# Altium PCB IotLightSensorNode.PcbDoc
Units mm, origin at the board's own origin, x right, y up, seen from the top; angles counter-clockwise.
Board outline 63 x 63 mm, 2 copper layers (Top Layer, Bottom Layer); 28 components, 22 nets, 90 pads, 15 vias.
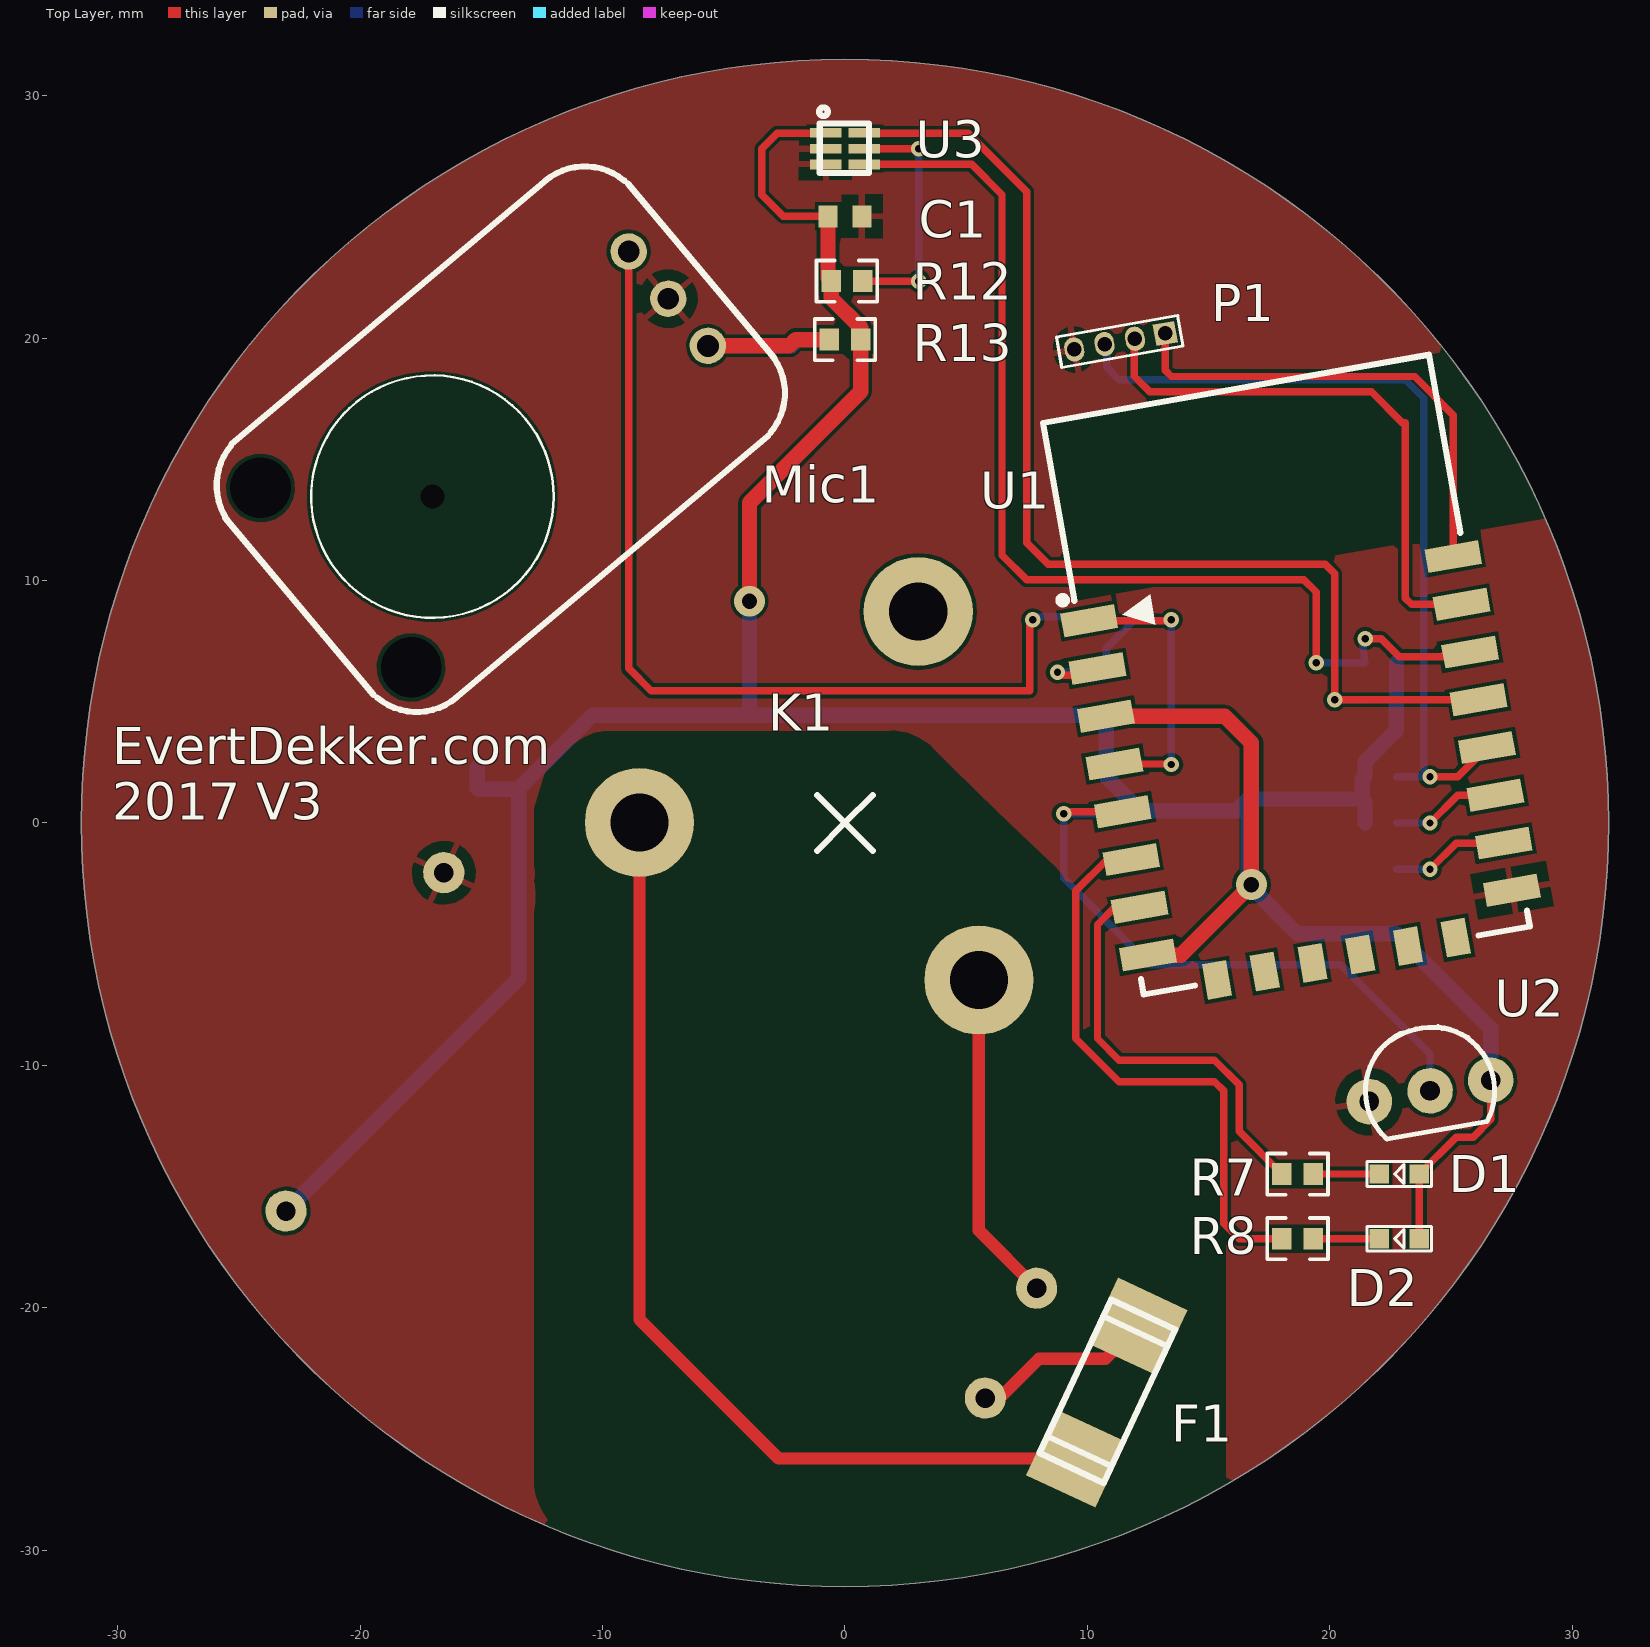
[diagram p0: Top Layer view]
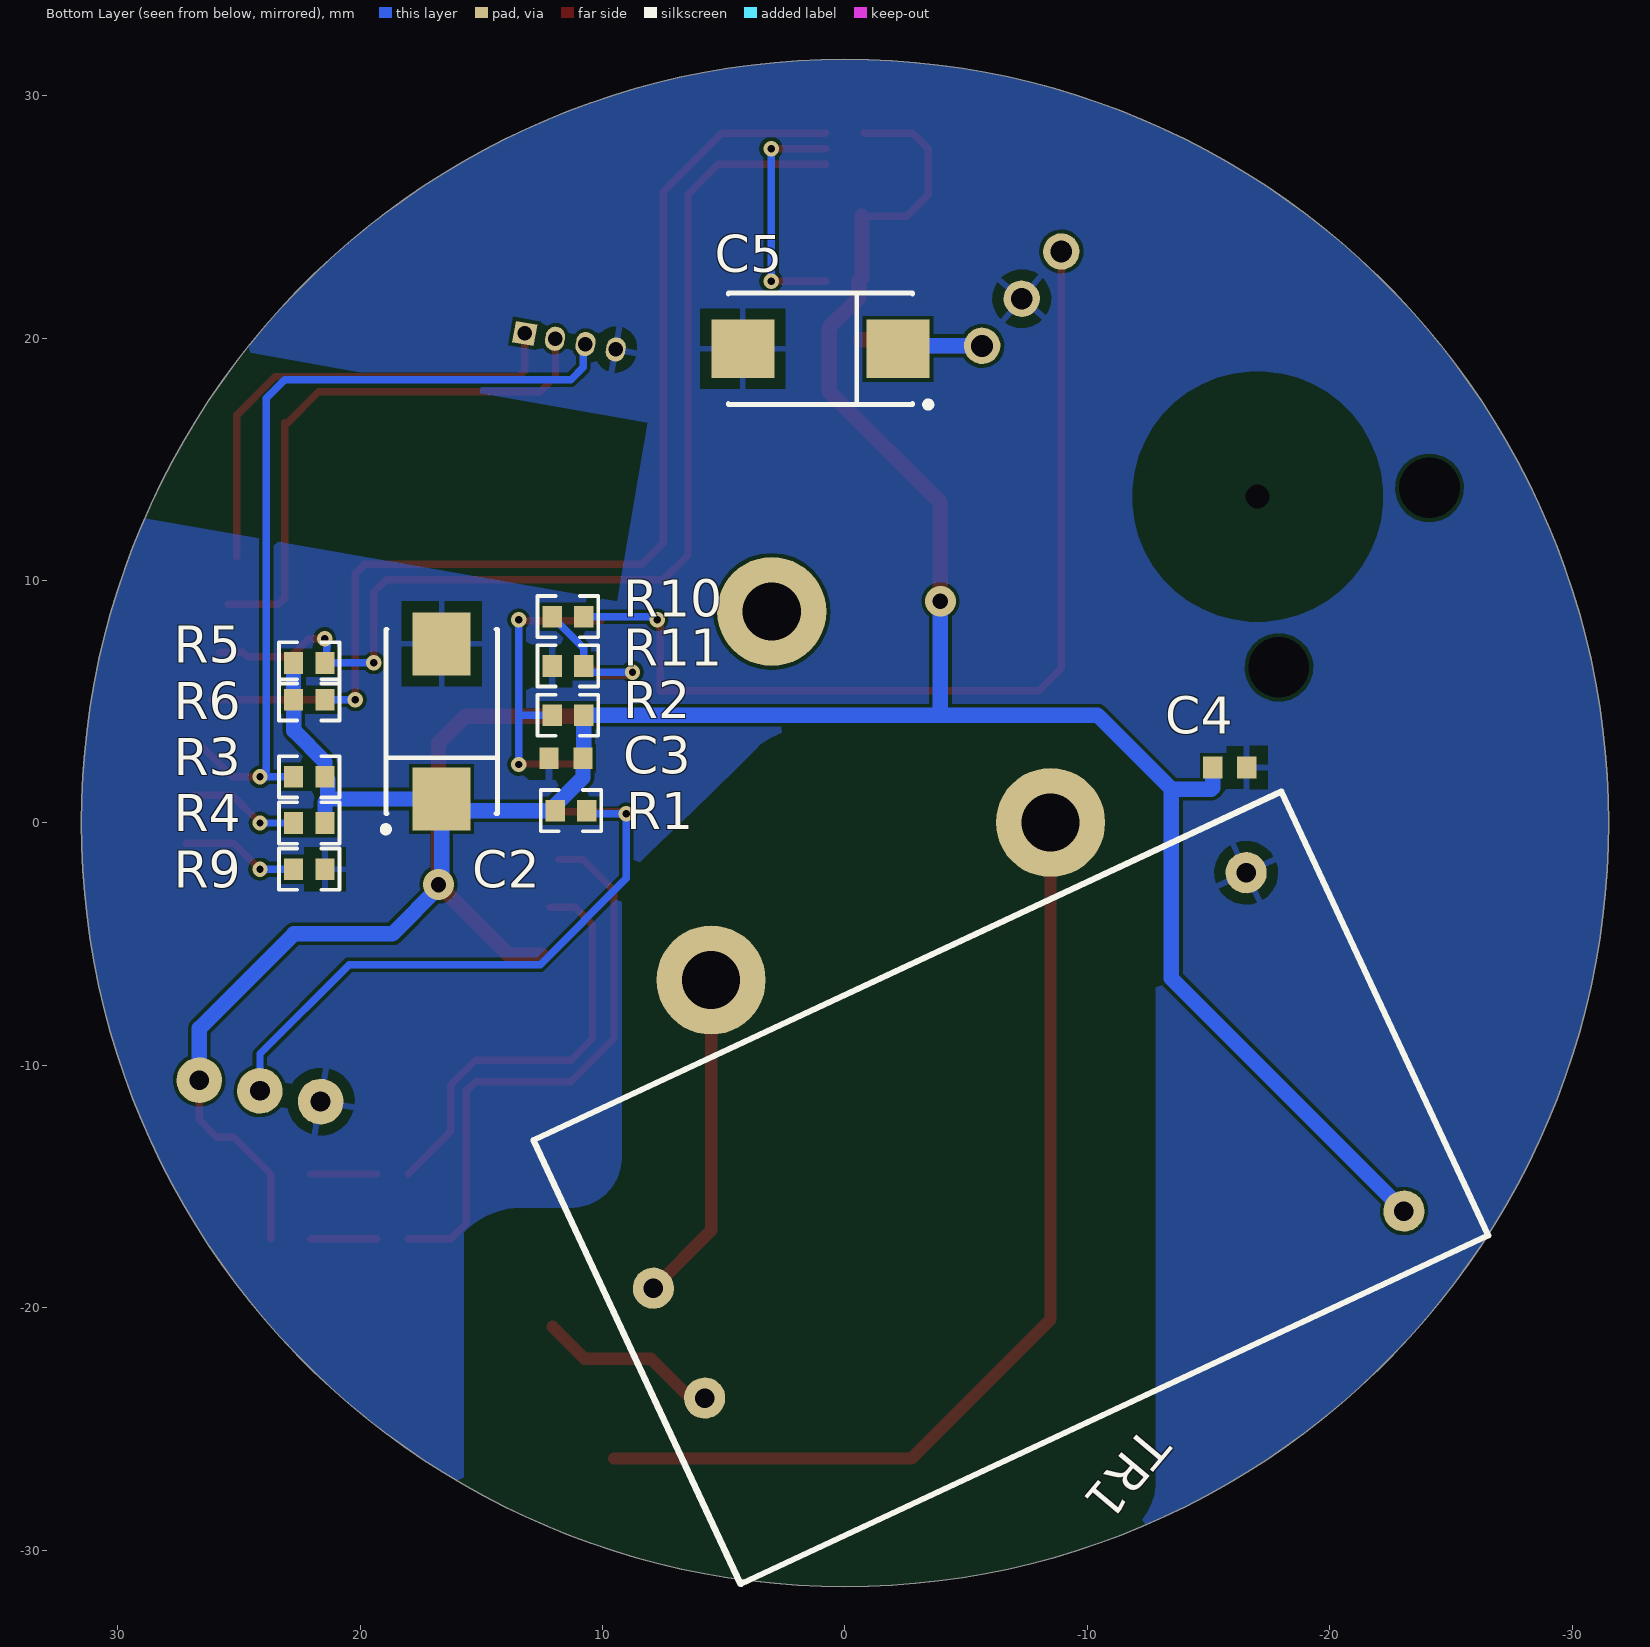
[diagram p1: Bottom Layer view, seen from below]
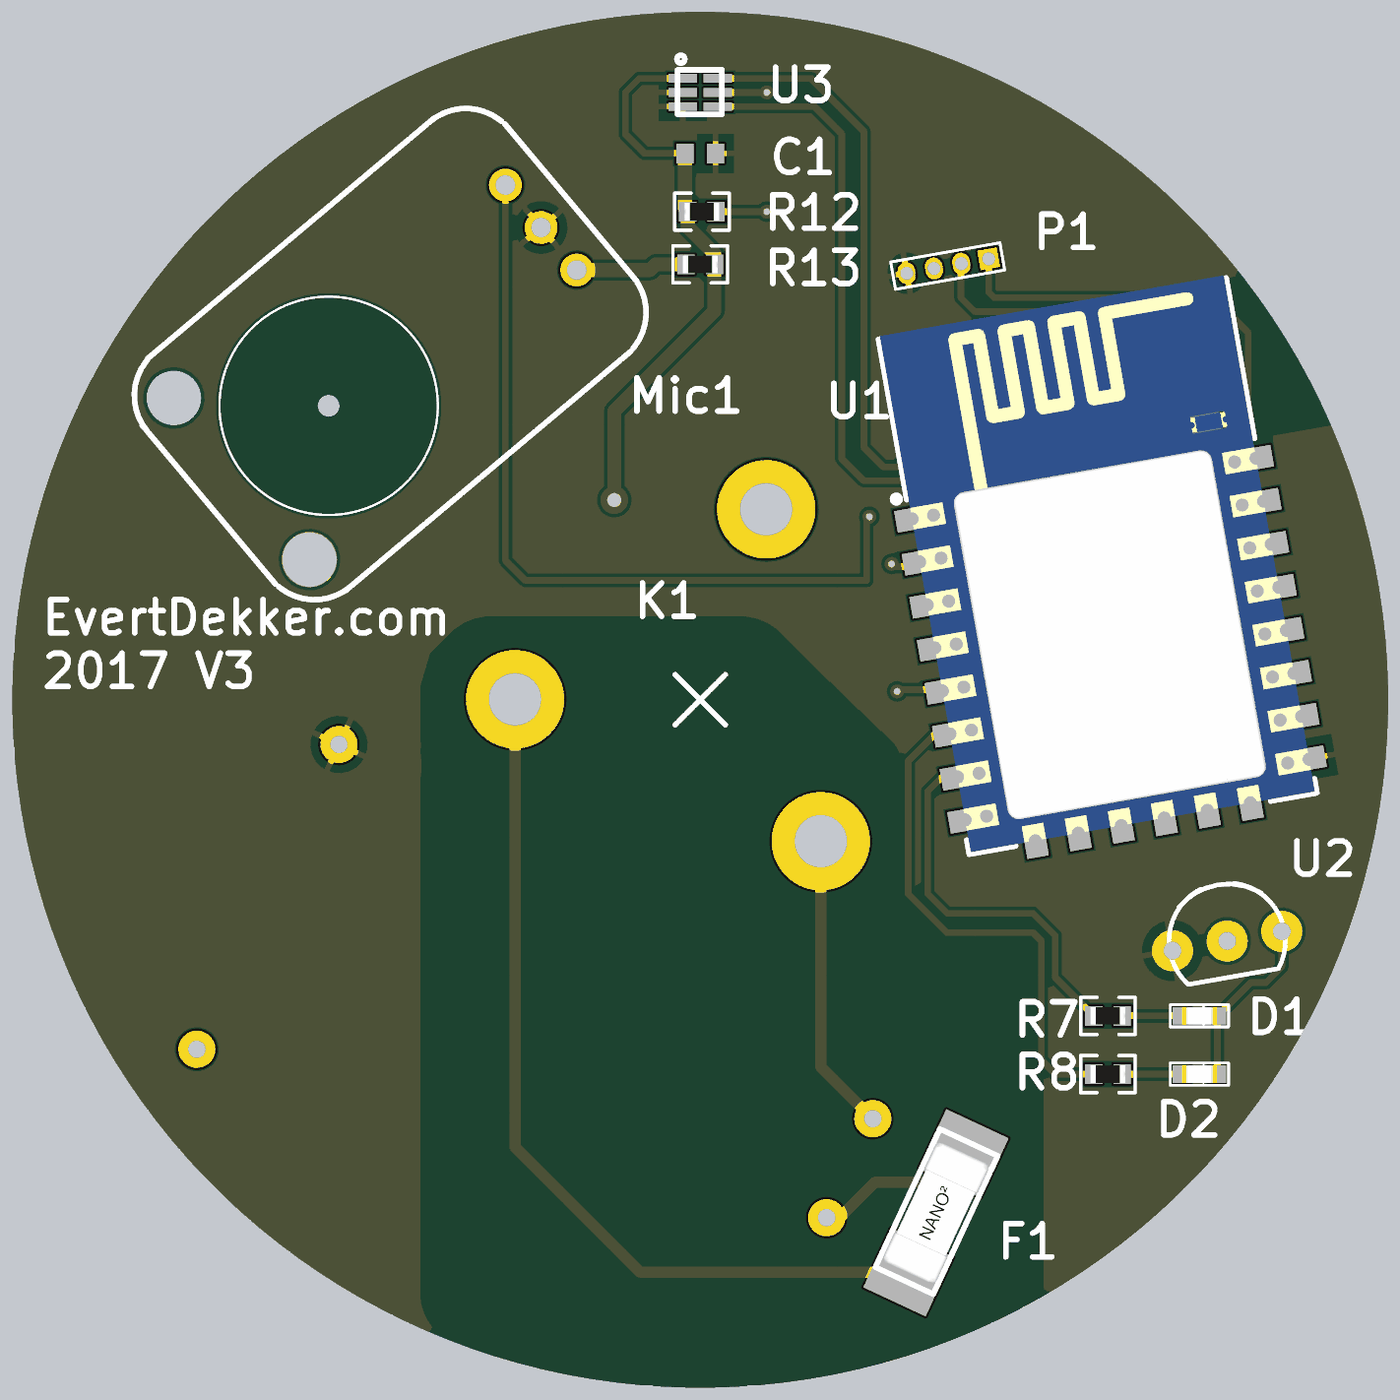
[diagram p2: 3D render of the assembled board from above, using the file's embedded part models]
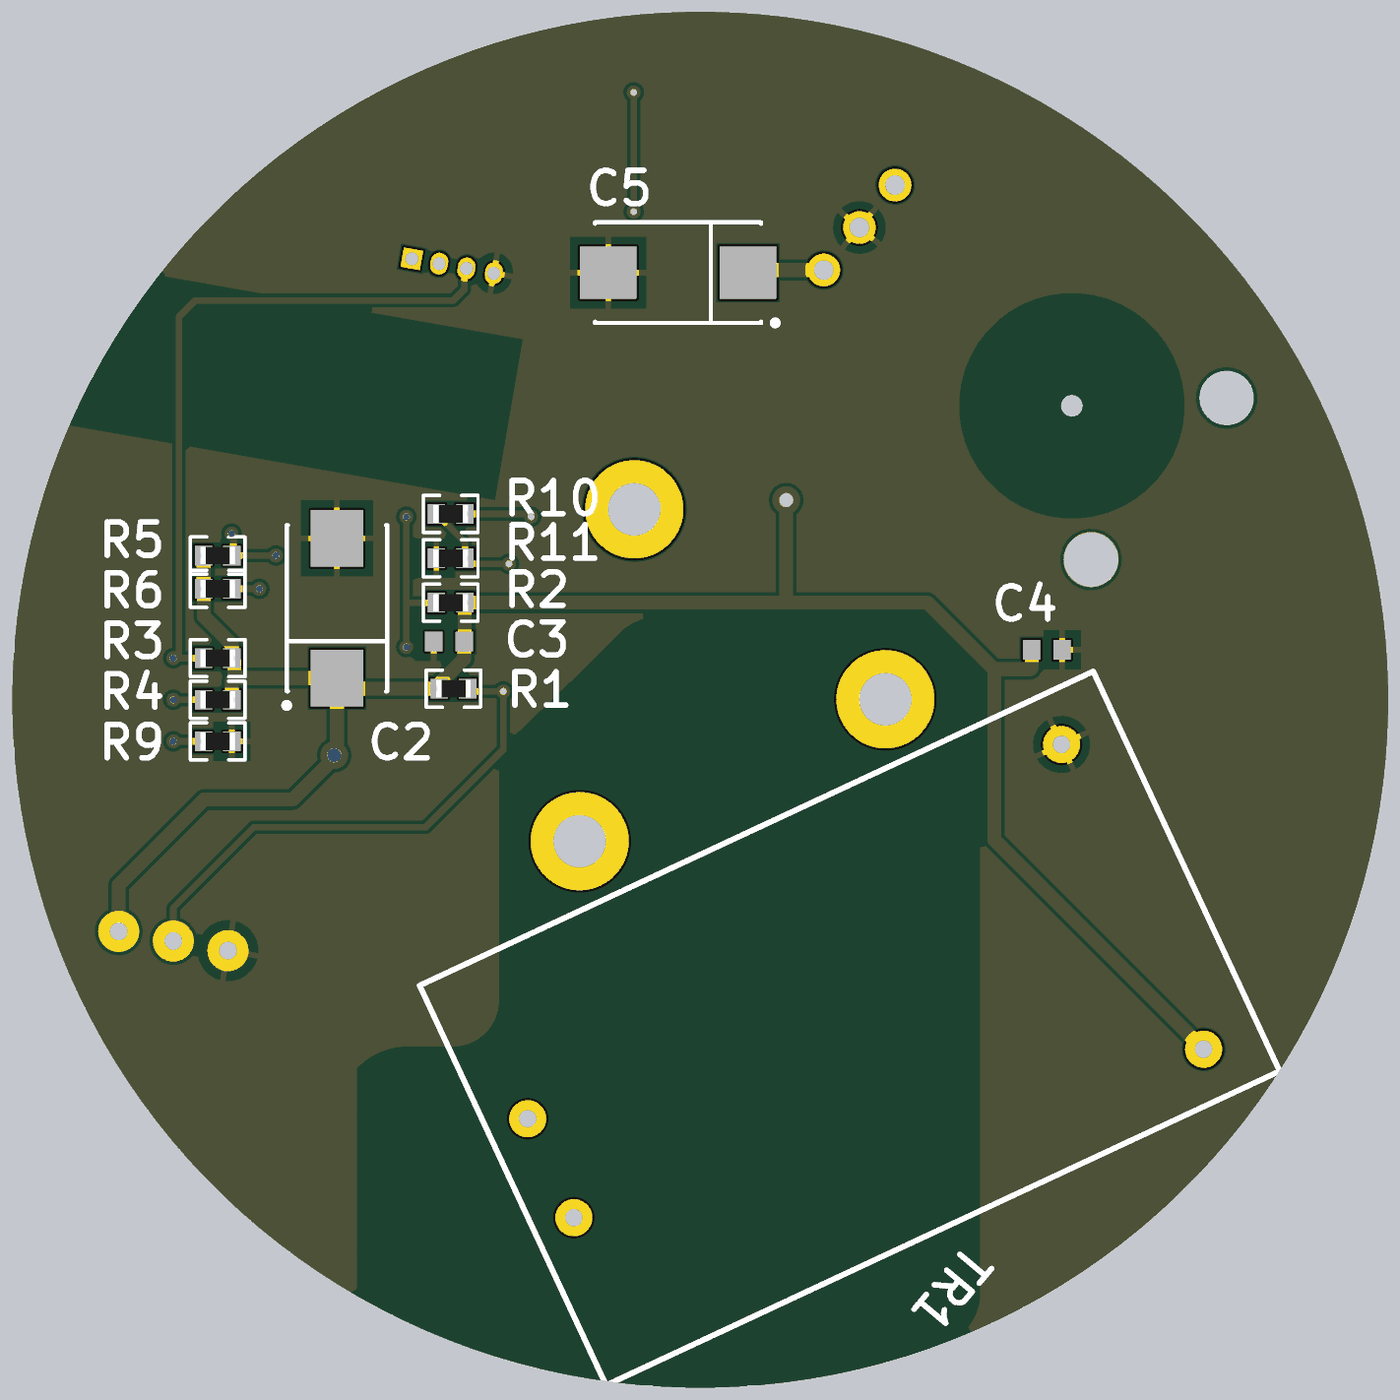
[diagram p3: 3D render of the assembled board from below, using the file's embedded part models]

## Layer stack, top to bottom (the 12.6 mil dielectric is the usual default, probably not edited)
Top Solder: solder mask 0.0102, Solder Resist, Dk 3.5
Top Layer: signal copper 0.0356
Dielectric 1: dielectric 0.32, FR-4, Dk 4.8
Bottom Layer: signal copper 0.0356
Bottom Solder: solder mask 0.0102, Solder Resist, Dk 3.5

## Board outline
-31.5,0 ccw(c0,0) 0,-31.5 ccw(c0,0) 31.5,0 ccw(c0,0) 0,31.5 ccw(c0,0)

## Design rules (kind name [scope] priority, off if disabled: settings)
AssemblyTestPointUsage SilkToBoardRegionClearance_1 [All] p2:
Clearance [All] p1: gap=0.152
MatchedLengths DiffPair_DIFF100MatchedLengths [InDifferentialPairClass('DIFF100')] p1: tolerance=0.152 checknetsindiffpair=TRUE checkdiffpairvsdiffpair=FALSE checkxsignals=FALSE checkothers=FALSE
MinimumSolderMaskSliver SilkscreenOverComponentPads_1 [All] p1: minsoldermaskwidth=0.254
MinimumSolderMaskSliver SilkToSolderMaskClearance_1 [IsPad] p2: minsoldermaskwidth=0.254
MinimumSolderMaskSliver [All] p3: minsoldermaskwidth=0.254
MinimumSolderMaskSliver SilkscreenOverComponentPads [All] p4: minsoldermaskwidth=0.254
PolygonConnect [All] p1: connectstyle=Relief reliefconductorwidth=0.254 reliefentries=4 polygonreliefangle="90 Angle" airgapwidth=0.454
RoutingVias [All] p1: holewidth=0.305 width=0.635 viastyle="Through Hole" minholewidth=0.305 minwidth=0.635 maxholewidth=0.711 maxwidth=1.27
SilkToSolderMaskClearance SilkToSolderMaskClearance_2 [IsPad] p1: minsilkscreentomaskgap=0.254 clearancetoexposedcopper=TRUE
SilkToSolderMaskClearance [IsPad] p2: minsilkscreentomaskgap=0.254 clearancetoexposedcopper=TRUE
SolderMaskExpansion [All] p1: expansion=0.102
Width [All] p1: maxlimit=2.54 minlimit=0.152 preferedwidth=0.254
28 further rules are at their usual default settings.

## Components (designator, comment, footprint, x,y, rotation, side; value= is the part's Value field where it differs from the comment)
C1 "Cap Semi" 1608[0603] 0,25.019 r180 top
C2 "T491X" X 16.637,4.191 r90 bottom
C3 "Cap Semi" 1608[0603] 11.506,2.667 r180 bottom
C4 "Cap Semi" 1608[0603] -15.875,2.286 r0 bottom
C5 "T491X" X 1.016,19.558 r0 bottom
D1 "Led Red" LED1608 22.86,-14.478 r180 top
D2 "Led Blue" LED1608 22.86,-17.145 r180 top
F1 "Fuse" SmdFuse1808 10.795,-23.495 r65 top
K1 "ZC145200" ZC145200 0,0 r0 top
Mic1 "Max4466_module" MAX446_Module -17.018,13.462 r40 top
P1 "Prog" Header4x1.27mm 13.208,20.193 r190 top
R1 "Resistor" RES0603R 11.303,0.508 r180 bottom
R2 "Resistor" RES0603R 11.43,4.445 r0 bottom
R3 "Resistor" RES0603R 22.098,1.905 r0 bottom
R4 "Resistor" RES0603R 22.098,0 r0 bottom
R5 "Resistor" RES0603R 22.098,6.604 r180 bottom
R6 "Resistor" RES0603R 22.098,5.08 r180 bottom
R7 "Resistor" RES0603R 18.669,-14.478 r180 top
R8 "Resistor" RES0603R 18.669,-17.145 r180 top
R9 "Resistor" RES0603R 22.098,-1.905 r180 bottom
R10 "Resistor" RES0603R 11.43,8.509 r0 bottom
R11 "Resistor" RES0603R 11.43,6.477 r0 bottom
R12 "Resistor" RES0603R 0.076,22.352 r0 top
R13 "Resistor" RES0603R 0,19.939 r180 top
TR1 "HLK-PM03" HLK-PM03 -6.477,-15.24 r155 bottom
U1 "ESP_12_E" ESP_12_E 18.923,2.032 r10 top
U2 "DS18B20" TO-92-AMMO 24.13,-11.049 r10 top
U3 "TSL2561" DFN6-2x2 0,27.813 r0 top

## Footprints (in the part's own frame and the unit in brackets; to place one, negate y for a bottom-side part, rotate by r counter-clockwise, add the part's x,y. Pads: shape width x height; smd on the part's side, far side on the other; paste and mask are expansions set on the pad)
1608[0603] [mm] "Chip Capacitor, Body 1.6x0.8mm, IPC High Density"
  rect 0.8x0.9 smd: 1(-0.7,0) 2(0.7,0)
  body extent -0.87,-0.48 0.87,0.48, height 1.3
DFN6-2x2 [mm] "TSL256x Package FN"
  rect 1.3x0.4 smd: 1(-0.8,0.65) 2(-0.8,0) 3(-0.8,-0.65) 4(0.8,-0.65) 5(0.8,0) 6(0.8,0.65)
  silkscreen extent -1.07,-1 0.99,1.7
ESP_12_E [mm] "ESP-12 Wi-Fi Module by AI-Thinker"
  rect 2.25x1 smd: 1(-7.625,7.75) 2(-7.625,5.75) 3(-7.625,3.75) 4(-7.625,1.75) 5(-7.625,-0.25) 6(-7.625,-2.25) 7(-7.625,-4.25) 8(-7.625,-6.25) 15(7.62,-6.223) 16(7.625,-4.25) 17(7.625,-2.25) 18(7.625,-0.25) 19(7.625,1.75) 20(7.625,3.75) 21(7.625,5.75) 22(7.625,7.75)
  rect 1x1.5 smd: 9(-5,-7.75) 10(-3,-7.75) 11(-1,-7.75) 12(1,-7.75) 13(3,-7.75) 14(5,-7.75)
  silkscreen extent -8.7,-7.82 8.08,16.12, body extent -8,-7.74 8,16.26, height 2.75
Header4x1.27mm [mm]
  rect 0.9x0.9 hole 0.6: 1(0,0)
  oval 0.8x1 hole 0.6: 2(1.27,0) 3(2.54,0) 4(3.81,0)
  silkscreen extent -0.64,-0.64 4.45,0.64
HLK-PM03 [mm] "Hi-Link HLK-PM03 Power Module"
  round 1.7 hole 0.8: 1(-14.7,2.5) 2(-14.7,-2.5) 3(14.7,7.7) 4(14.7,-7.7)
  silkscreen extent -16.61,-10.08 17.43,10.12, body extent -16.61,-10.07 17.43,10.12, height 15
LED1608 [mm] "1608"
  rect 0.8x0.8 smd: A(-0.826,0) K(0.826,0)
  silkscreen extent -1.33,-0.51 1.33,0.51, body extent -0.8,-0.4 0.8,0.4, height 1.11
MAX446_Module [mm] "Adafruit MAX 4466 Mic Amp"
  round 0 hole 1 unplated: 0(0,0)
  round 1.5 hole 0.9: 1(12.7,-2.54) 2(12.7,2.54) 3(12.7,0)
  round 1.5 hole 2.5 unplated: 12(-5.2,4.83)
  round 1.5 hole 2.5: 13(-5.2,-4.83)
  silkscreen extent -7.11,-6.99 14.48,6.99
RES0603R [mm] "resistor 0603 reflow soldering"
  rect 0.8x0.9 smd: 1(-0.65,0) 2(0.65,0)
  silkscreen extent -1.25,-0.85 1.25,0.85, body extent -0.8,-0.4 0.8,0.4, height 0.45
SmdFuse1808 [mm] "Smd Fuse 1808 Hand Solder"
  rect 3x3.15 smd: 1(-3,0) 2(3,0)
  silkscreen extent -3.43,-1.46 3.56,1.46, body extent -3.05,-1.35 3.05,1.35, height 2.7
TO-92-AMMO [mil]
  round 74 hole 32 mask-1000: 1(-100,0) 2(0,0) 3(100,0)
  silkscreen extent -105,-65 105,103
X [mm] "Capacitor, SM Tantalum; Body 7.3 x 4.3 mm (LxW typ)"
  rect 2.6x2.4 smd: 1(-3.2,0) 2(3.2,0)
  silkscreen extent -4.57,-2.3 3.8,2.43
ZC145200 [mm]
  round 4.5 hole 2.4: 1(-8.479,0.021) 2(5.521,-6.479) 3(3.021,8.721)
  silkscreen extent -1.14,-1.14 1.14,1.14

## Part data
C1 C3 C4: "Capacitor (Semiconductor SIM Model)"
C2 C5: "Solid Tantalum Chip Capacitor, Standard T491 Series - Industrial Grade"
D1 D2: library part Led
K1: "ZC145000 LightSensor"
P1: library part Header4x1.27mm
TR1: "Hi-Link HLK-PM03 3.3VDC/3W Power Module"
U1: "ESP-12 Wi-Fi Module by AI-Thinker"
U2: "Temp%20Sensor%20Digital%20Serial%20%281-Wire%29%203-Pin%20TO-92%20T/R"

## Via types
v1: diameter 0.635, hole 0.305, Top Layer to Bottom Layer, 13 vias
v2: diameter 1.27, hole 0.635, Top Layer to Bottom Layer, 2 vias

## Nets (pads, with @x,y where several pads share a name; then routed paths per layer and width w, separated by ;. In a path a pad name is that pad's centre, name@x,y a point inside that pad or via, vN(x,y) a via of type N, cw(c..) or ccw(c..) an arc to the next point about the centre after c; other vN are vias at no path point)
GND: C1.1 C2.2 C3.1 C4.1 C5.2 Mic1.3 P1.4 R9.2 R11.2 TR1.3 U1.15 U2.1 U3.2 U3.3
NetC5_1: C5.1 Mic1.1 R13.2 | length 8.6
  Top Layer w0.635: Mic1.1 -2.291,19.68 -2.032,19.939 R13.2
  Bottom Layer w0.635: Mic1.1 C5.1@-2.179,19.68
NetD1_2: D1.K R7.1 | length 2.7
  Top Layer w0.305: R7.1 D1.K
NetD2_2: D2.K R8.1 | length 2.7
  Top Layer w0.305: R8.1 D2.K
NetF1_1: F1.1 K1.1 | length 40.9
  Top Layer w0.508: K1.1 -8.479,-20.477 -2.742,-26.214 F1.1
NetF1_2: F1.2 TR1.2 | length 7.5
  Top Layer w0.254: TR1.2 TR1.2@6.381,-23.718
  Top Layer w0.508: TR1.2@6.381,-23.718 8.001,-22.098 10.741,-22.098 F1.2
NetK1_2: K1.2 TR1.1 | length 13.7
  Top Layer w0.508: K1.2 5.521,-16.805 TR1.1
NetMic1_2: Mic1.2 R10.1 | length 40.2
  Top Layer w0.305: Mic1.2 -8.922,6.382 -8.001,5.461 7.62,5.461 7.62,8.382 v1(7.747,8.382)
  Bottom Layer w0.305: v1(7.747,8.382) 7.874,8.509 R10.1
NetP1_1: P1.1 U1.22 | length 20
  Top Layer w0.305: P1.1 13.208,18.669 13.462,18.415 23.495,18.415 25.086,16.824 U1.22
NetP1_2: P1.2 U1.21 | length 23.2
  Top Layer w0.305: P1.2 11.938,19.953 11.938,18.415 12.573,17.78 21.717,17.78 22.987,16.51 23.114,16.51 23.114,9.271 23.366,9.019 U1.21
NetP1_3: P1.3 R3.2 U1.18 | length 34.6
  Top Layer w0.305: v1(24.13,1.905) 25.271,1.905 U1.18
  Bottom Layer w0.305: P1.3 10.795,19.664 10.795,18.796 11.303,18.288 23.114,18.288 23.876,17.526 23.876,2.159 v1(24.13,1.905) R3.2
NetR1_2: R1.2 U1.5 U2.2 | length 26.5
  Top Layer w0.305: v1(9.017,0.381) 9.098,0.462 U1.5
  Bottom Layer w0.305: R1.2 10.526,0.381 v1(9.017,0.381) 9.017,-2.286 12.573,-5.842 20.447,-5.842 24.13,-9.525 U2.2
NetR2_2: R2.2 U1.1 U1.4 | length 13.1
  Top Layer w0.305: U1.1 13.42,8.34 v1(13.462,8.382) ; U1.4 13.444,2.431 v1(13.462,2.413)
  Bottom Layer w0.305: R2.2 13.462,4.445 ; v1(13.462,2.413) 13.462,4.445 ; v1(13.462,8.382) 13.462,4.445
NetR4_2: R4.2 U1.17 | length 4.5
  Top Layer w0.305: v1(24.13,0) 25.27,1.14 U1.17
  Bottom Layer w0.305: R4.2 v1(24.13,0)
NetR7_2: R7.2 U1.7 | length 17.8
  Top Layer w0.305: U1.7 11.128,-3.477 10.414,-4.191 10.414,-8.89 11.303,-9.779 15.24,-9.779 16.256,-10.795 16.256,-12.715 R7.2
NetR8_2: R8.2 U1.6 | length 24
  Top Layer w0.305: U1.6 10.811,-1.508 9.525,-2.794 9.525,-8.89 11.303,-10.668 15.24,-10.668 15.621,-11.049 15.621,-16.51 16.256,-17.145 R8.2
NetR9_1: R9.1 U1.16 | length 4.9
  Top Layer w0.305: v1(24.13,-1.905) 25.206,-0.829 U1.16
  Bottom Layer w0.305: R9.1 v1(24.13,-1.905)
NetR10_2: R10.2 R11.1 U1.2 | length 6.5
  Top Layer w0.305: v1(8.763,6.223) 8.89,6.096 10.141,6.096 U1.2
  Bottom Layer w0.305: v1(8.763,6.223) 10.526,6.223 R11.1 10.78,7.209 R10.2
NetR12_2: R12.2 U3.5 | length 10
  Top Layer w0.305: R12.2@0.777,22.352 v1(3.048,22.352) ; U3.5 v1(3.048,27.813)
  Bottom Layer w0.305: v1(3.048,22.352) v1(3.048,27.813)
SCL: R5.2 U1.20 U3.4 | length 45.3
  Top Layer w0.305: U3.4 5.222,27.163 6.477,25.908 6.477,11.049 7.493,10.033 18.923,10.033 19.431,9.525 v1(19.431,6.604) ; v1(21.463,7.605) 22.113,7.605 22.86,6.858 24.638,6.858 24.829,7.049 U1.20
  Bottom Layer w0.305: v1(19.431,6.604) R5.2 21.336,7.478 v1(21.463,7.605)
SDA: R6.2 U1.19 U3.6 | length 47.8
  Top Layer w0.305: U3.6 0.815,28.448 5.08,28.448 7.493,26.035 7.493,11.557 8.382,10.668 19.812,10.668 20.193,10.287 v1(20.193,5.08) 22.606,5.08 U1.19
  Bottom Layer w0.305: v1(20.193,5.08) R6.2
VCC: C1.2 C2.1 C3.2 C4.2 D1.A D2.A R1.1 R2.1 R3.1 R4.1 R5.1 R6.1 R12.1 R13.1 TR1.4 U1.3 U1.8 U2.3 U3.1 | length 145.6
  Top Layer w0.305: U3.1 -0.815,28.448 -2.794,28.448 -3.429,27.813 -3.429,25.908 -2.54,25.019 C1.2 ; D2.A D1.A 25.209,-12.954 25.908,-12.954 26.631,-12.231 U2.3
  Top Layer w0.635: v2(-3.937,9.144) -3.937,13.208 0.65,17.795 R13.1 0.65,20.432 -0.574,21.656 R12.1 -0.7,22.478 C1.2 ; U1.3 15.665,4.401 16.764,3.302 v2(16.764,-2.54) 13.857,-5.447 U1.8
  Bottom Layer w0.635: TR1.4 -13.462,-6.414 -13.462,1.397 ; C4.2 -15.175,1.459 -15.113,1.397 -13.462,1.397 ; v2(-3.937,9.144) -3.937,4.445 ; v2@16.637,-2.54 C2.1 ; v2@16.7,-2.603 18.669,-4.572 22.733,-4.572 26.631,-8.47 U2.3 ; R4.1 21.448,0.854 21.311,0.991 ; R5.1 R6.1 22.733,5.065 22.733,3.81 21.448,2.525 R3.1 21.336,1.793 21.336,1.016 21.311,0.991 ; -13.462,1.397 -10.414,4.445 -5.588,4.445 -3.937,4.445 ; -3.937,4.445 R2.1 10.78,2.693 C3.2 10.806,1.869 11.953,0.723 R1.1 16.154,0.508 C2.1 ; C2.1 21.311,0.991
pads on no net: K1.3 Mic1.0 Mic1.12 Mic1.13 U1.9 U1.10 U1.11 U1.12 U1.13 U1.14

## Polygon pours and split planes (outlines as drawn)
GND on Top Layer "GND_L01_P002" (solid, remove dead copper, pour order 2): -31.5,0 ccw(c0,0) 0,-31.5 ccw(c0,0) 31.5,0 ccw(c0,0) 0,31.5 ccw(c0,0)
GND on Bottom Layer "Top Layer-No Net" (solid, pour order 3): -31.5,0 ccw(c0,0) 0,-31.5 ccw(c0,0) 31.5,0 ccw(c0,0) 0,31.5 ccw(c0,0)

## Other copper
Top Layer:
  pour cut-out: 8.078,16.501 24.715,19.422 28.906,12.564 9.348,9.135
  pour cut-out: -17.018,8.305 cw(c-17.018,13.462) -22.175,13.462 cw(c-17.018,13.462) -17.018,18.619 cw(c-17.018,13.462) -11.861,13.462 cw(c-17.018,13.462)
  pour cut-out: 15.73,-21.536 15.73,-16.891 ccw(c13.352,-19.163) 13.426,-15.875 11.176,-15.875 cw(c11.309,-13.78) 9.214,-13.647 9.214,-2.731 ccw(c7.522,-3.092) 8.709,-1.833 cw(c173.546,172.945) 3.665,3.066 ccw(c1.869,1.271) 1.869,3.81 -9.616,3.81 ccw(c-9.616,1.271) -11.412,3.066 -12.383,2.095 -12.827,0.599 -12.827,-1.778 cw(c-14.366,-2.085) -12.827,-2.391 cw(c-16.07,-3.037) -12.827,-3.683 -12.827,-15.24 -12.827,-27.14 ccw(c-10.293,-27.14) -11.226,-29.496 ccw(c-4.571,-12.688) -8.47,-30.34 -4.406,-31.238 1.396,-31.583 ccw(c0.855,-7.758) 8.47,-30.34 11.633,-29.273 14.478,-27.976 ccw(c13.856,-25.947) 15.73,-26.942 15.73,-22.225
Bottom Layer:
  pour cut-out: 8.128,16.51 24.765,19.431 28.956,12.573 9.398,9.144
  pour cut-out: -17.018,8.305 cw(c-17.018,13.462) -22.175,13.462 cw(c-17.018,13.462) -17.018,18.619 cw(c-17.018,13.462) -11.861,13.462 cw(c-17.018,13.462)
  pour cut-out: 15.73,-21.536 15.73,-16.891 ccw(c13.352,-19.163) 13.426,-15.875 11.176,-15.875 cw(c11.309,-13.78) 9.214,-13.647 9.214,-2.731 ccw(c7.522,-3.092) 8.709,-1.833 cw(c173.546,172.945) 3.665,3.066 ccw(c1.869,1.271) 1.869,3.81 -9.616,3.81 ccw(c-9.616,1.271) -11.412,3.066 -12.383,2.095 -12.827,0.599 -12.827,-1.778 cw(c-14.366,-2.085) -12.827,-2.391 cw(c-16.07,-3.037) -12.827,-3.683 -12.827,-15.24 -12.827,-27.14 ccw(c-10.293,-27.14) -11.226,-29.496 ccw(c-4.571,-12.688) -8.47,-30.34 -4.406,-31.238 1.396,-31.583 ccw(c0.855,-7.758) 8.47,-30.34 11.633,-29.273 14.478,-27.976 ccw(c13.856,-25.947) 15.73,-26.942 15.73,-22.225

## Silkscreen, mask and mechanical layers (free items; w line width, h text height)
Top Overlay:
  text "EvertDekker.com / 2017 V3" at -30.226,0.127 h1.52
Mechanical 1:
  circle w0.254: c0,0 r31.5
Milling:
  circle w5: c-17.018,13.462 r2.5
